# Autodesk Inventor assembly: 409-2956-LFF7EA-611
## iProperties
Created: 2010-06
Part Number: 409-2956-LFF7EA-611
Document SubType Name: Weldment
Designer: S. Boerckel
Weld Material: Welded Aluminum-6061
Mass: 82652.4 g
Surface Area: 20244 cm^2
Volume: 10533.7 cm^3
Density: 7.84648 g/cm^3
Description: PUMP MOUNT
User Status: WELD
Material: WELDMENT
SMR: =<Material>
Author: S. Boerckel
Revision Number: 0
Subject: LIQUID FUEL FORWARDING PUMP SKID-7EA
